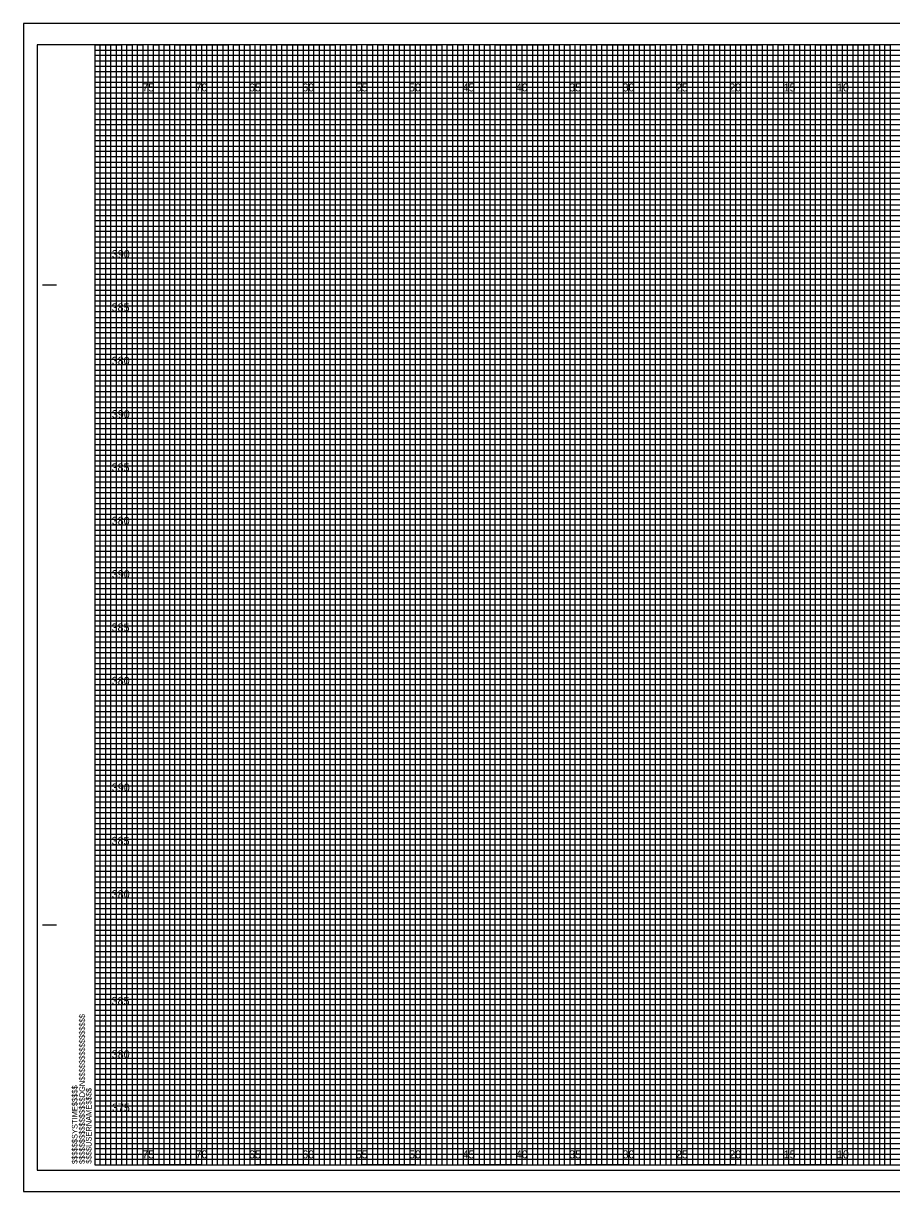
# Model space of a CAD drawing. Extents: x -7 to 162, y -2 to 107.
# Drawn here: x -6.7 to 74.6, y -2.5 to 107 of the extents above; entities that cross this region are included whole.
import ezdxf

# ---------------------------------------------------------------- set-up
doc = ezdxf.new("R2010")
doc.units = 0
for name, color, linetype in [('Prop XS Elevation Labels', 7, 'Continuous'), ('Prop XS Offset Labels', 7, 'Continuous'), ('Sheet Cross Section CELL', 7, 'Continuous'), ('Sheet Cross Section Grid Major CELL', 7, 'Continuous'), ('Sheet Cross Section Grid Middle CELL', 7, 'Continuous'), ('Sheet Cross Section Grid Minor 1 CELL', 7, 'Continuous'), ('Sheet Cross Section Grid Minor 2 CELL', 7, 'Continuous'), ('Sheet Plot Border Inside CELL', 7, 'Continuous'), ('Sheet Plot Border Outside CELL', 7, 'Continuous')]:
    doc.layers.add(name, color=color, linetype=linetype)

msp = doc.modelspace()

# ---------------------------------------------------------------- linework, layer by layer
at = {"layer": 'Sheet Cross Section CELL'}
for p, q in [((-4.9, 82.5), (-3.65, 82.5)), ((-4.85, 82.5), (-3.6, 82.5)), ((-4.9, 22.5), (-3.65, 22.5)), ((-4.85, 22.5), (-3.6, 22.5)), ((0, 0), (0, 0)), ((0, 0), (0, 0)), ((0, 0), (0, 0)), ((0, 0), (0, 0)), ((0, 0), (0, 0)), ((0, 0), (0, 0)), ((0, 0), (0, 0))]:
    msp.add_line(p, q, dxfattribs=at)
msp.add_lwpolyline([(160, 105), (0, 105), (0, 0), (160, 0)], close=True, dxfattribs=at)
at = {"layer": 'Sheet Cross Section Grid Major CELL'}
for p, q in [((5, 105), (0, 105)), ((5, 0), (5, 105)), ((15, 105), (10, 105)), ((10, 105), (10, 0)), ((15, 0), (15, 105)), ((25, 105), (20, 105)), ((20, 105), (20, 0)), ((25, 0), (25, 105)), ((35, 105), (30, 105)), ((30, 105), (30, 0)), ((35, 0), (35, 105)), ((45, 105), (40, 105)), ((40, 105), (40, 0)), ((45, 0), (45, 105)), ((55, 105), (50, 105)), ((50, 105), (50, 0)), ((55, 0), (55, 105)), ((65, 105), (60, 105)), ((60, 105), (60, 0)), ((65, 0), (65, 105)), ((75, 105), (70, 105)), ((70, 105), (70, 0)), ((10, 0), (5, 0)), ((20, 0), (15, 0)), ((30, 0), (25, 0)), ((40, 0), (35, 0)), ((60, 0), (55, 0)), ((70, 0), (65, 0)), ((50, 0), (45, 0))]:
    msp.add_line(p, q, dxfattribs=at)
for points in [[(160, 102.5), (160, 95), (0, 95)], [(0, 100), (160, 100)], [(0, 90), (160, 90), (160, 85), (0, 85)], [(0, 80), (160, 80), (160, 75), (0, 75)], [(0, 70), (160, 70), (160, 65), (0, 65)], [(0, 60), (160, 60), (160, 55), (0, 55)], [(0, 50), (160, 50), (160, 45), (0, 45)], [(0, 40), (160, 40), (160, 35), (0, 35)], [(0, 30), (160, 30), (160, 25), (0, 25)], [(0, 20), (160, 20), (160, 15), (0, 15)], [(0, 10), (160, 10), (160, 5), (0, 5)]]:
    msp.add_lwpolyline(points, dxfattribs=at)
at = {"layer": 'Sheet Cross Section Grid Middle CELL'}
for points in [[(0, 105), (2.5, 105), (2.5, 0), (7.5, 0), (7.5, 105), (12.5, 105), (12.5, 0), (17.5, 0), (17.5, 105), (22.5, 105), (22.5, 0), (27.5, 0), (27.5, 105), (32.5, 105), (32.5, 0), (37.5, 0), (37.5, 105), (42.5, 105), (42.5, 0), (47.5, 0), (47.5, 105), (52.5, 105), (52.5, 0), (57.5, 0), (57.5, 105), (62.5, 105), (62.5, 0), (67.5, 0), (67.5, 105), (72.5, 105), (72.5, 0), (77.5, 0)], [(0, 102.5), (137.5, 102.5)], [(0, 92.5), (160, 92.5), (160, 102.5)], [(160, 97.5), (0, 97.5)], [(0, 82.5), (160, 82.5), (160, 87.5), (0, 87.5)], [(0, 72.5), (160, 72.5), (160, 77.5), (0, 77.5)], [(0, 62.5), (160, 62.5), (160, 67.5), (0, 67.5)], [(0, 52.5), (160, 52.5), (160, 57.5), (0, 57.5)], [(0, 42.5), (160, 42.5), (160, 47.5), (0, 47.5)], [(0, 32.5), (160, 32.5), (160, 37.5), (0, 37.5)], [(0, 22.5), (160, 22.5), (160, 27.5), (0, 27.5)], [(0, 12.5), (160, 12.5), (160, 17.5), (0, 17.5)], [(0, 2.5), (160, 2.5), (160, 7.5), (0, 7.5)]]:
    msp.add_lwpolyline(points, dxfattribs=at)
at = {"layer": 'Sheet Cross Section Grid Minor 1 CELL'}
for p, q in [((0, 104.5), (110.95, 104.5)), ((110.95, 103.99), (0, 103.99)), ((0, 103.99), (0, 103.5)), ((0, 103.5), (110.95, 103.5)), ((110.95, 102.95), (0, 102.95)), ((0, 102.95), (0, 102)), ((0, 102), (160, 102))]:
    msp.add_line(p, q, dxfattribs=at)
for points in [[(0, 101.5), (135, 101.5), (160, 101.5)], [(160, 101), (0, 101)], [(0, 100.5), (160, 100.5)], [(160, 99.5), (0, 99.5)], [(0, 99), (160, 99)], [(160, 98.5), (0, 98.49)], [(0, 98), (160, 98)], [(160, 97), (0, 97)], [(0, 96.5), (160, 96.5), (160, 96), (0, 96)], [(0, 95.5), (160, 95.5), (160, 94.5), (0, 94.5)], [(0, 94), (160, 94), (160, 93.5), (0, 93.5)], [(0, 93), (160, 93), (160, 92), (0, 92)], [(0, 91.5), (160, 91.5), (160, 91), (0, 91)], [(0, 90.5), (160, 90.5), (160, 89.5), (0, 89.5)], [(0, 89), (160, 89), (160, 88.5), (0, 88.5)], [(0, 88), (160, 88), (160, 86.97), (160, 86.5), (160, 86), (0, 86)], [(0, 87), (160, 87), (160, 86.5), (0, 86.5)], [(0, 85.5), (160, 85.5), (160, 84.5), (0, 84.51)], [(0, 84.51), (160, 84.5), (160, 84), (0, 84)], [(0, 83.5), (160, 83.5), (160, 83), (0, 83)], [(0, 82), (160, 82), (160, 81.5), (0, 81.5)], [(0, 81), (160, 81), (160, 80.5), (0, 80.5)], [(-0.04, 79.44), (160, 79.44), (160, 78.94), (-0.04, 78.94)], [(0, 78.5), (160, 78.5), (160, 78), (0, 78)], [(0, 77), (160, 77), (160, 76.5), (0, 76.5)], [(0, 76), (160, 76), (160, 75.5), (0, 75.5)], [(0, 74.5), (160, 74.5), (160, 74), (0, 74)], [(0, 73.5), (160, 73.5), (160, 73), (0, 73)], [(0, 72), (160, 72), (160, 71.5), (0, 71.5)], [(0, 71), (160, 71), (160, 70.5), (0, 70.5)], [(0, 69.5), (160, 69.5), (159.99, 68.99), (0, 69)], [(0, 68.5), (160, 68.5), (160, 68), (0, 68)], [(0, 67), (160, 67), (160, 66.5), (0, 66.5)], [(0, 66), (160, 66), (160, 65.5), (0, 65.5)], [(0, 64.5), (160, 64.5), (160, 64), (0, 64)], [(0, 63.5), (160, 63.5), (160, 63), (0, 63)], [(0, 62), (160, 62), (160, 61.5), (0, 61.5)], [(0, 61), (160, 61), (160, 60.5), (0, 60.5)], [(0, 59.5), (160, 59.5), (160, 59), (0, 59)], [(0, 58.5), (160.03, 58.45), (160, 58), (0, 58)], [(0, 57), (160, 57), (160, 56.5), (0, 56.5)], [(0, 56), (160, 56), (160, 55.5), (0, 55.5)], [(0, 54.5), (160, 54.5), (160, 54), (0, 54)], [(0, 53.5), (160, 53.5), (160, 53), (0, 53)], [(0, 52), (160, 52), (160, 51.5), (0, 51.5)], [(0, 51), (160, 51), (160, 50.5), (0, 50.5)], [(0, 49.5), (160, 49.5), (160, 49), (0, 49)], [(0, 48.5), (160, 48.5), (160, 48), (0, 48)], [(0, 47), (160, 47), (160, 46.5), (0, 46.5)], [(0, 46), (160, 46), (160, 45.5), (0, 45.5)], [(0, 44.5), (160, 44.5), (160, 44), (0, 44)], [(0, 43.5), (160, 43.5), (160, 43), (0, 43)], [(0, 42), (160, 42), (160, 41.5), (0, 41.5)], [(0, 41), (160, 41), (160, 40.5), (0, 40.5)], [(0, 39.5), (160, 39.5), (159.99, 38.99), (0, 39)], [(0, 38.5), (160, 38.5), (160, 38), (0, 38)], [(0, 37), (160, 37), (160, 36.5), (0, 36.5)], [(0, 36), (160, 36), (160, 35.5), (0, 35.5)], [(0, 34.5), (160, 34.5), (160, 34), (0, 34)], [(0, 33.5), (160, 33.5), (160, 33), (0, 33)], [(0, 32), (160, 32), (160, 31.5), (0, 31.5)], [(0, 31), (160, 31), (160, 30.5), (0, 30.5)], [(0, 29.5), (160, 29.5), (160, 29), (0, 29)], [(0, 28.5), (160.03, 28.46), (160, 28), (0, 28)], [(0, 27), (160, 27), (160, 26.5), (0, 26.5)], [(0, 26), (160, 26), (160, 25.5), (0, 25.5)], [(0, 24.5), (160, 24.5), (160, 24), (0, 24)], [(0, 23.5), (160, 23.5), (160, 23), (0, 23)], [(0, 22), (160, 22), (160, 21.5), (0, 21.5)], [(0, 21), (160, 21), (160, 20.5), (0, 20.5)], [(0, 19.5), (160, 19.5), (160, 19), (0, 19)], [(0, 18.5), (160, 18.5), (160, 18), (0, 18)], [(0, 17), (160, 17), (160, 16.5), (0, 16.5)], [(0, 16), (160, 16), (160, 15.5), (0, 15.5)], [(0, 14.5), (160, 14.5), (160, 14), (0, 14)], [(0, 13.5), (160, 13.5), (160, 13), (0, 13)], [(0, 12), (160, 12), (160, 11.5), (0, 11.5)], [(0, 11), (160, 11), (160, 10.5), (0, 10.5)], [(0, 9.5), (160, 9.5), (160, 9), (0, 9)], [(0, 8.5), (160, 8.5), (160, 8), (0, 8)], [(0, 7), (160, 7), (160, 6.5), (0, 6.5)], [(0, 6), (160, 6), (160, 5.5), (0, 5.5)], [(0, 4.5), (160, 4.5), (160, 4), (0, 4)], [(0, 3.5), (160, 3.5), (160, 3), (0, 3)], [(0, 2), (160, 2), (160, 1.5), (0, 1.5)], [(0, 1), (160, 1), (160, 0.5), (0, 0.5)]]:
    msp.add_lwpolyline(points, dxfattribs=at)
at = {"layer": 'Sheet Cross Section Grid Minor 2 CELL'}
for points in [[(0, 0), (0.5, 0), (0.5, 105), (1, 105), (1, 0)], [(1, 0), (1.5, 0), (1.5, 105), (2, 105), (2, 0)], [(2.5, 0), (3, 0), (3, 105), (3.5, 105), (3.5, 0)], [(3.5, 0), (4, 0), (4, 105), (4.5, 105), (4.5, 0)], [(5, 0), (5.5, 0), (5.5, 105), (6, 105), (6, 0)], [(6, 0), (6.5, 0), (6.5, 105), (7, 105), (7, 0)], [(7.5, 0), (8, 0), (8, 105), (8.5, 105), (8.5, 0)], [(8.5, 0), (9, 0), (9, 105), (9.5, 105), (9.5, 0)], [(10, 0), (10.5, 0), (10.5, 105), (11, 105), (11, 0)], [(11, 0), (11.5, 0), (11.5, 105), (12, 105), (12, 0)], [(12.5, 0), (13, 0), (13, 105), (13.5, 105), (13.5, 0)], [(13.5, 0), (14, 0), (14, 105), (14.5, 105), (14.5, 0)], [(15, 0), (15.5, 0), (15.5, 105), (16, 105), (16, 0)], [(16, 0), (16.5, 0), (16.5, 105), (17, 105), (17, 0)], [(17.5, 0), (18, 0), (18, 105), (18.5, 105), (18.5, 0)], [(18.5, 0), (19, 0), (19, 105), (19.5, 105), (19.5, 0)], [(20, 0), (20.5, 0), (20.5, 105), (21, 105), (21, 0)], [(21, 0), (21.5, 0), (21.5, 105), (22, 105), (22, 0)], [(22.5, 0), (23, 0), (23, 105), (23.5, 105), (23.5, 0)], [(23.5, 0), (24, 0), (24, 105), (24.5, 105), (24.5, 0)], [(25, 0), (25.5, 0), (25.5, 105), (26, 105), (26, 0)], [(26, 0), (26.5, 0), (26.5, 105), (27, 105), (27, 0)], [(27.5, 0), (28, 0), (28, 105), (28.5, 105), (28.5, 0)], [(28.5, 0), (29, 0), (29, 105), (29.5, 105), (29.5, 0)], [(30, 0), (30.5, 0), (30.5, 105), (31, 105), (31, 0)], [(31, 0), (31.5, 0), (31.5, 105), (32, 105), (32, 0)], [(32.5, 0), (33, 0), (33, 105), (33.5, 105), (33.5, 0)], [(33.5, 0), (34, 0), (34, 105), (34.5, 105), (34.5, 0)], [(35, 0), (35.5, 0), (35.5, 105), (36, 105), (36, 0)], [(36, 0), (36.5, 0), (36.5, 105), (37, 105), (37, 0)], [(37.5, 0), (38, 0), (38, 105), (38.5, 105), (38.5, 0)], [(38.5, 0), (39, 0), (39, 105), (39.5, 105), (39.5, 0)], [(40, 0), (40.5, 0), (40.5, 105), (41, 105), (41, 0)], [(41, 0), (41.5, 0), (41.5, 105), (42, 105), (42, 0)], [(42.5, 0), (43, 0), (43, 105), (43.5, 105), (43.5, 0)], [(43.5, 0), (44, 0), (44, 105), (44.5, 105), (44.5, 0)], [(45, 0), (45.5, 0), (45.5, 105), (46, 105), (46, 0)], [(46, 0), (46.5, 0), (46.5, 105), (47, 105), (47, 0)], [(47.5, 0), (48, 0), (48, 105), (48.5, 105), (48.5, 0)], [(48.5, 0), (49, 0), (49, 105), (49.5, 105), (49.5, 0)], [(50, 0), (50.5, 0), (50.5, 105), (51, 105), (51, 0)], [(51, 0), (51.5, 0), (51.5, 105), (52, 105), (52, 0)], [(52.5, 0), (53, 0), (53, 105), (53.5, 105), (53.5, 0)], [(53.5, 0), (54, 0), (54, 105), (54.5, 105), (54.5, 0)], [(55, 0), (55.5, 0), (55.5, 105), (56, 105), (56, 0)], [(56, 0), (56.5, 0), (56.5, 105), (57, 105), (57, 0)], [(57.5, 0), (58, 0), (58, 105), (58.5, 105), (58.5, 0)], [(58.5, 0), (59, 0), (59, 105), (59.5, 105), (59.5, 0)], [(60, 0), (60.5, 0), (60.5, 105), (61, 105), (61, 0)], [(61, 0), (61.5, 0), (61.5, 105), (62, 105), (62, 0)], [(62.5, 0), (63, 0), (63, 105), (63.5, 105), (63.5, 0)], [(63.5, 0), (64, 0), (64, 105), (64.5, 105), (64.5, 0)], [(65, 0), (65.5, 0), (65.5, 105), (66, 105), (66, 0)], [(66, 0), (66.5, 0), (66.5, 105), (67, 105), (67, 0)], [(67.5, 0), (68, 0), (68, 105), (68.5, 105), (68.5, 0)], [(68.5, 0), (69, 0), (69, 105), (69.5, 105), (69.5, 0)], [(70, 0), (70.5, 0), (70.5, 105), (71, 105), (71, 0)], [(71, 0), (71.5, 0), (71.5, 105), (72, 105), (72, 0)], [(72.5, 0), (73, 0), (73, 105), (73.5, 105), (73.5, 0)], [(73.5, 0), (74, 0), (74, 105), (74.5, 105), (74.5, 0)]]:
    msp.add_lwpolyline(points, dxfattribs=at)
at = {"layer": 'Sheet Plot Border Inside CELL'}
msp.add_lwpolyline([(-5.4, -0.5), (161.2, -0.5), (161.2, 105), (-5.4, 105)], close=True, dxfattribs=at)
at = {"layer": 'Sheet Plot Border Outside CELL'}
msp.add_lwpolyline([(-6.7, -2.5), (161.65, -2.5), (161.65, 107), (-6.7, 107)], close=True, dxfattribs=at)

# ---------------------------------------------------------------- texts
at = {"layer": 'Prop XS Elevation Labels'}
for s, p in [('390', (1.59, 85)), ('385', (1.57, 80)), ('380', (1.58, 75)), ('390', (1.59, 70)), ('385', (1.57, 65)), ('380', (1.58, 60)), ('390', (1.59, 55)), ('385', (1.57, 50)), ('380', (1.58, 45)), ('390', (1.59, 35)), ('385', (1.57, 30)), ('380', (1.58, 25)), ('385', (1.57, 15)), ('380', (1.58, 10)), ('375', (1.6, 5))]:
    msp.add_text(s, height=0.75, dxfattribs=at).set_placement(p)
at = {"layer": 'Prop XS Offset Labels'}
for s, p in [('75', (4.44, 100.62)), ('70', (9.43, 100.62)), ('65', (14.44, 100.62)), ('60', (19.43, 100.62)), ('55', (24.44, 100.62)), ('50', (29.43, 100.62)), ('45', (34.44, 100.62)), ('40', (39.43, 100.62)), ('35', (44.44, 100.62)), ('30', (49.43, 100.62)), ('25', (54.44, 100.62)), ('20', (59.43, 100.62)), ('15', (64.53, 100.62)), ('10', (69.52, 100.62)), ('75', (4.44, 0.62)), ('70', (9.43, 0.62)), ('65', (14.44, 0.62)), ('60', (19.43, 0.62)), ('55', (24.44, 0.62)), ('50', (29.43, 0.62)), ('45', (34.44, 0.62)), ('40', (39.43, 0.62)), ('35', (44.44, 0.62)), ('30', (49.43, 0.62)), ('25', (54.44, 0.62)), ('20', (59.43, 0.62)), ('15', (64.53, 0.62)), ('10', (69.52, 0.62))]:
    msp.add_text(s, height=0.75, dxfattribs=at).set_placement(p)
at = {"layer": 'Sheet Cross Section CELL'}
for s, p in [('$$$$$$$$$$$$$$$$DGN$$$$$$$$$$$$$$$$', (-0.94, 0.09)), ('$$$$$$SYSTIME$$$$$', (-1.63, 0.09)), ('$$$$USERNAME$$$$', (-0.31, 0.12))]:
    msp.add_text(s, height=0.525, rotation=90, dxfattribs=at).set_placement(p)

doc.saveas('drawing.dxf')
